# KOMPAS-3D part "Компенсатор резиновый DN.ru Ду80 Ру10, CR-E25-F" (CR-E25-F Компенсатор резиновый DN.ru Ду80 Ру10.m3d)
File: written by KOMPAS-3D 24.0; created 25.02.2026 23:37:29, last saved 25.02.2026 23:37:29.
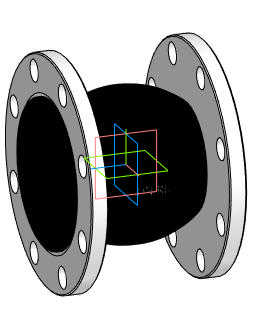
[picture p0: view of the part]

Document properties: Автор: DN.RU; Полное имя файла: D:\PROJECT CAD\DN.RU\...178(4)(ACTUALE). CR-E25-F Компенсатор резиновый DN.ru Ру10-16\DN80_PN16\CR-E25-F Компенсатор резиновый DN.ru Ду80 Ру10.m3d

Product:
- Body: Твердое тело2  | qty 1
    Масса: 8.814168
- Part/product: Компенсатор резиновый DN.ru Ду80 Ру10  | designation CR-E25-F
    Масса: 7.04
    Раздел спецификации: Прочие изделия
    Комментарий: D140-02175
    Примечание: D140-02175
    additional columns: Типовые

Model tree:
1. Твердое тело2  (labels: Твердое тело2)

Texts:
  CR-E25-F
